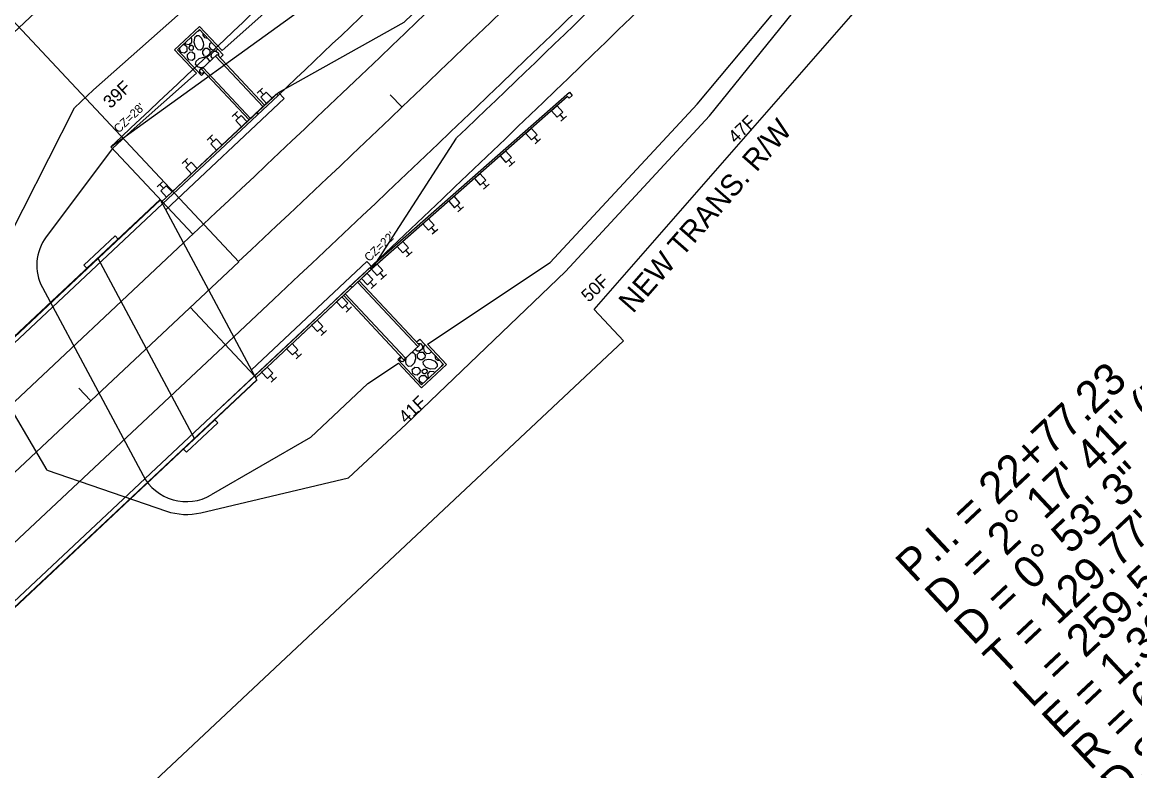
# Model space of a CAD drawing. Extents: x 1623239 to 1625698, y 1118659 to 1120751.
# Drawn here: x 1624416.9 to 1624676.8, y 1119574.5 to 1119749.3 of the extents above; entities that cross this region are included whole.
import ezdxf

# ---------------------------------------------------------------- set-up
doc = ezdxf.new("R2010")
doc.units = 0
for name, color, linetype in [('BR_CONCRETE', 7, 'Continuous'), ('BR_PROPOSED_TRAVELWAY', 7, 'Continuous'), ('Default', 7, 'Continuous'), ('Drainage-Trench', 7, 'Continuous'), ('RD_HC_CL_Rel', 7, 'Continuous'), ('RD_HC_Data', 7, 'Continuous'), ('RD_HC_Data_Tic', 7, 'Continuous'), ('RD_PD_BOC', 7, 'Continuous'), ('RD_PD_CstnLmt', 7, 'Continuous'), ('RD_PD_CstnLmt_TX', 7, 'Continuous'), ('RD_PD_DR_ErosCtrl', 7, 'Continuous'), ('RD_PD_Final_TrvlWay', 7, 'Continuous'), ('RD_PD_GR', 7, 'Continuous'), ('RD_PD_PaveDit', 7, 'Continuous'), ('RD_PD_PaveShd', 7, 'Continuous'), ('RD_PD_RW', 7, 'Continuous'), ('RD_Sketch8', 7, 'Continuous')]:
    doc.layers.add(name, color=color, linetype=linetype)

# ---------------------------------------------------------------- blocks, each defined once
blk = doc.blocks.new('Guardrail_MTBBC3_Transition')
at = {"layer": 'RD_PD_GR'}
for p, q in [((3.525, 3.75), (1.775, 3.75)), ((2.65, 2.5), (2.65, 3.75)), ((11.525, 3.75), (9.775, 3.75)), ((10.65, 2.5), (10.65, 3.75)), ((19.525, 3.75), (17.775, 3.75)), ((18.65, 2.5), (18.65, 3.75)), ((27.525, 3.75), (25.775, 3.75)), ((26.65, 2.5), (26.65, 3.75)), ((35.525, 3.75), (33.775, 3.75)), ((34.65, 2.5), (34.65, 3.75)), ((37, 0.5), (0, 0.5)), ((0, 0.5), (0, 0)), ((0, 0), (37, 0)), ((1.775, 0.5), (1.775, 2.5)), ((1.775, 2.5), (3.525, 2.5)), ((3.525, 0.5), (1.775, 0.5)), ((3.525, 2.5), (3.525, 0.5)), ((9.775, 0.5), (9.775, 2.5)), ((9.775, 2.5), (11.525, 2.5)), ((11.525, 0.5), (9.775, 0.5)), ((11.525, 2.5), (11.525, 0.5)), ((17.775, 0.5), (17.775, 2.5)), ((17.775, 2.5), (19.525, 2.5)), ((19.525, 0.5), (17.775, 0.5)), ((19.525, 2.5), (19.525, 0.5)), ((25.775, 0.5), (25.775, 2.5)), ((25.775, 2.5), (27.525, 2.5)), ((27.525, 0.5), (25.775, 0.5)), ((27.525, 2.5), (27.525, 0.5)), ((30.65, 0.5), (30.65, 0)), ((33.775, 0.5), (33.775, 2.5)), ((33.775, 2.5), (35.525, 2.5)), ((35.525, 0.5), (33.775, 0.5)), ((35.525, 2.5), (35.525, 0.5)), ((37, 0), (37, 0.5))]:
    blk.add_line(p, q, dxfattribs=at)

msp = doc.modelspace()

# ---------------------------------------------------------------- linework, layer by layer
at = {"layer": 'BR_CONCRETE'}
for p, q in [((1624343.39, 1119608.68), (1624449.15, 1119707.87)), ((1624343.45, 1119608.57), (1624449.22, 1119707.76)), ((1624343.94, 1119607.65), (1624449.7, 1119706.85)), ((1624449.15, 1119707.87), (1624471.75, 1119665.66)), ((1624434.57, 1119694.19), (1624457.17, 1119651.98)), ((1624365.44, 1119567.5), (1624471.2, 1119666.69)), ((1624365.93, 1119566.58), (1624471.69, 1119665.77)), ((1624365.99, 1119566.47), (1624471.75, 1119665.66))]:
    msp.add_line(p, q, dxfattribs=at)
for points in [[(1624432.01, 1119691.8), (1624431.33, 1119692.53), (1624438.62, 1119699.37), (1624439.31, 1119698.64)], [(1624455.3, 1119648.85), (1624454.61, 1119649.58), (1624461.91, 1119656.42), (1624462.59, 1119655.69)]]:
    msp.add_lwpolyline(points, close=True, dxfattribs=at)
at = {"layer": 'BR_PROPOSED_TRAVELWAY'}
for p, q in [((1624348.83, 1119598.53), (1624454.59, 1119697.72)), ((1624360.55, 1119576.62), (1624466.32, 1119675.81))]:
    msp.add_line(p, q, dxfattribs=at)
at = {"layer": 'Default'}
msp.add_line((1624365.44, 1119567.5), (1624471.2, 1119666.69), dxfattribs=at)
at = {"layer": 'Drainage-Trench'}
for p, q in [((1624453.22, 1119742.79), (1624458.32, 1119747.58)), ((1624463.88, 1119741.65), (1624458.32, 1119747.58)), ((1624458.77, 1119736.86), (1624453.22, 1119742.79)), ((1624458.82, 1119738.28), (1624462.47, 1119741.7)), ((1624462.1, 1119741.36), (1624473.18, 1119729.54)), ((1624462.47, 1119741.7), (1624473.54, 1119729.89)), ((1624463.15, 1119740.97), (1624463.88, 1119741.65)), ((1624458.77, 1119736.86), (1624459.5, 1119737.55)), ((1624458.82, 1119738.28), (1624469.9, 1119726.47)), ((1624459.18, 1119738.62), (1624470.26, 1119726.81)), ((1624509.36, 1119673.53), (1624495.26, 1119688.56)), ((1624509.73, 1119673.87), (1624495.63, 1119688.91)), ((1624506.08, 1119670.45), (1624491.98, 1119685.49)), ((1624506.45, 1119670.79), (1624492.35, 1119685.83)), ((1624509.05, 1119674.6), (1624509.77, 1119675.28)), ((1624509.77, 1119675.28), (1624515.33, 1119669.36)), ((1624506.08, 1119670.45), (1624509.73, 1119673.87)), ((1624504.67, 1119670.5), (1624505.4, 1119671.18)), ((1624504.67, 1119670.5), (1624510.22, 1119664.57)), ((1624510.22, 1119664.57), (1624515.33, 1119669.36))]:
    msp.add_line(p, q, dxfattribs=at)
at = {"layer": 'RD_HC_CL_Rel'}
msp.add_line((1624334.12, 1119568.29), (1624467.48, 1119693.35), dxfattribs=at)
msp.add_arc((1620034.69, 1124419.96), 6480, 313.16267, 315.457254, dxfattribs=at)
at = {"layer": 'RD_HC_Data'}
msp.add_line((1624467.48, 1119693.35), (1624367.16, 1119800.32), dxfattribs=at)
at = {"layer": 'RD_HC_Data_Tic'}
for p, q in [((1624505.66, 1119729.45), (1624502.9, 1119732.34)), ((1624432.86, 1119660.89), (1624430.12, 1119663.8))]:
    msp.add_line(p, q, dxfattribs=at)
at = {"layer": 'RD_PD_BOC'}
for p, q in [((1624449.36, 1119707.21), (1624476.75, 1119732.89)), ((1624476.75, 1119732.89), (1624478.11, 1119731.43)), ((1624478.11, 1119731.43), (1624450.44, 1119705.48)), ((1624497.46, 1119693.37), (1624470.47, 1119668.06)), ((1624498.83, 1119691.91), (1624497.46, 1119693.37)), ((1624471.45, 1119666.23), (1624498.83, 1119691.91))]:
    msp.add_line(p, q, dxfattribs=at)
at = {"layer": 'RD_PD_CstnLmt'}
for p, q in [((1624574.57, 1119730.15), (1624607.1, 1119768.89)), ((1624463.59, 1119742.69), (1624479.55, 1119756.84)), ((1624452.51, 1119742.81), (1624458.35, 1119748.28)), ((1624458.35, 1119748.28), (1624463.59, 1119742.69)), ((1624457.6, 1119737.39), (1624452.51, 1119742.81)), ((1624442.33, 1119723.86), (1624457.6, 1119737.39)), ((1624540.28, 1119693.12), (1624574.57, 1119730.15)), ((1624442.33, 1119723.86), (1624437.99, 1119719.78)), ((1624437.99, 1119719.78), (1624422.52, 1119699.13)), ((1624511.58, 1119674.09), (1624540.28, 1119693.12)), ((1624421.62, 1119687.33), (1624445.13, 1119643.41)), ((1624516.04, 1119669.34), (1624511.58, 1119674.09)), ((1624497.68, 1119664.88), (1624504.81, 1119669.61)), ((1624504.81, 1119669.61), (1624510.2, 1119663.87)), ((1624510.2, 1119663.87), (1624516.04, 1119669.34)), ((1624497.68, 1119664.88), (1624484.27, 1119652.31)), ((1624484.27, 1119652.31), (1624461.07, 1119638.88))]:
    msp.add_line(p, q, dxfattribs=at)
for centre, radius, start, end in [((1624431.33, 1119692.53), 11.01, 143.1621, 208.1627), ((1624455.3, 1119648.85), 11.53, 208.1627, 300.0691)]:
    msp.add_arc(centre, radius, start, end, dxfattribs=at)
at = {"layer": 'RD_PD_DR_ErosCtrl'}
for p, q in [((1624433.57, 1119733.46), (1624470.93, 1119766.57)), ((1624577.5, 1119727.43), (1624609.39, 1119766.95)), ((1624429.09, 1119729.26), (1624433.57, 1119733.46)), ((1624410.22, 1119692.05), (1624429.09, 1119729.26)), ((1624543.85, 1119691.09), (1624577.5, 1119727.43)), ((1624506.58, 1119655.4), (1624543.85, 1119691.09)), ((1624422.77, 1119644.63), (1624408.1, 1119669.48)), ((1624493.17, 1119642.83), (1624506.58, 1119655.4)), ((1624422.77, 1119644.63), (1624450.59, 1119635.11)), ((1624458.62, 1119634.71), (1624493.17, 1119642.83))]:
    msp.add_line(p, q, dxfattribs=at)
msp.add_arc((1624455.3, 1119648.85), 14.53, 251.1042, 283.2212, dxfattribs=at)
at = {"layer": 'RD_PD_Final_TrvlWay'}
for p, q in [((1624454.59, 1119697.72), (1624459.27, 1119702.11)), ((1624466.32, 1119675.81), (1624475.69, 1119684.6))]:
    msp.add_line(p, q, dxfattribs=at)
for radius in [6468, 6492]:
    msp.add_arc((1620034.69, 1124419.96), radius, 313.16267, 315.457254, dxfattribs=at)
at = {"layer": 'RD_PD_GR'}
for p, q in [((1624498.19, 1119692), (1624544.76, 1119732.93)), ((1624545.42, 1119732.18), (1624544.67, 1119731.52)), ((1624544.76, 1119732.93), (1624545.42, 1119732.18)), ((1624544.34, 1119731.89), (1624498.52, 1119691.62)), ((1624541.9, 1119729.75), (1624540.58, 1119728.59)), ((1624543.22, 1119728.25), (1624541.9, 1119729.75)), ((1624544.67, 1119731.52), (1624544.34, 1119731.89)), ((1624540.58, 1119728.59), (1624541.9, 1119727.09)), ((1624541.9, 1119727.09), (1624543.22, 1119728.25)), ((1624542.56, 1119727.67), (1624543.39, 1119726.73)), ((1624544.04, 1119727.31), (1624542.73, 1119726.15)), ((1624535.89, 1119724.47), (1624534.57, 1119723.31)), ((1624537.21, 1119722.96), (1624535.89, 1119724.47)), ((1624534.57, 1119723.31), (1624535.9, 1119721.81)), ((1624535.9, 1119721.81), (1624537.21, 1119722.96)), ((1624536.55, 1119722.39), (1624537.38, 1119721.45)), ((1624538.03, 1119722.03), (1624536.72, 1119720.87)), ((1624529.88, 1119719.18), (1624528.57, 1119718.03)), ((1624531.2, 1119717.68), (1624529.88, 1119719.18)), ((1624528.57, 1119718.03), (1624529.89, 1119716.53)), ((1624529.89, 1119716.53), (1624531.2, 1119717.68)), ((1624530.54, 1119717.1), (1624531.37, 1119716.17)), ((1624532.03, 1119716.74), (1624530.71, 1119715.59)), ((1624523.87, 1119713.9), (1624522.56, 1119712.75)), ((1624525.19, 1119712.4), (1624523.87, 1119713.9)), ((1624522.56, 1119712.75), (1624523.88, 1119711.25)), ((1624523.88, 1119711.25), (1624525.19, 1119712.4)), ((1624524.54, 1119711.82), (1624525.36, 1119710.88)), ((1624526.02, 1119711.46), (1624524.7, 1119710.31)), ((1624517.86, 1119708.62), (1624516.55, 1119707.47)), ((1624516.55, 1119707.47), (1624517.87, 1119705.96)), ((1624519.18, 1119707.12), (1624517.86, 1119708.62)), ((1624517.87, 1119705.96), (1624519.18, 1119707.12)), ((1624518.53, 1119706.54), (1624519.35, 1119705.6)), ((1624520.01, 1119706.18), (1624518.69, 1119705.02)), ((1624511.85, 1119703.34), (1624510.54, 1119702.18)), ((1624510.54, 1119702.18), (1624511.86, 1119700.68)), ((1624513.17, 1119701.84), (1624511.85, 1119703.34)), ((1624511.86, 1119700.68), (1624513.17, 1119701.84)), ((1624512.52, 1119701.26), (1624513.34, 1119700.32)), ((1624514, 1119700.9), (1624512.69, 1119699.74)), ((1624505.85, 1119698.06), (1624504.53, 1119696.9)), ((1624504.53, 1119696.9), (1624505.85, 1119695.4)), ((1624507.17, 1119696.56), (1624505.85, 1119698.06)), ((1624505.85, 1119695.4), (1624507.17, 1119696.56)), ((1624506.51, 1119695.98), (1624507.33, 1119695.04)), ((1624507.99, 1119695.62), (1624506.68, 1119694.46)), ((1624498.52, 1119691.62), (1624498.19, 1119692)), ((1624499.84, 1119692.78), (1624498.52, 1119691.62)), ((1624498.52, 1119691.62), (1624499.84, 1119690.12)), ((1624501.16, 1119691.27), (1624499.84, 1119692.78)), ((1624499.84, 1119690.12), (1624501.16, 1119691.27)), ((1624500.5, 1119690.7), (1624501.33, 1119689.76)), ((1624501.98, 1119690.34), (1624500.67, 1119689.18))]:
    msp.add_line(p, q, dxfattribs=at)
msp.add_arc((1620034.75, 1124419.9), 6458, 313.457809, 314.284639, dxfattribs=at)
at = {"layer": 'RD_PD_PaveDit'}
for p, q in [((1624459.46, 1119745.7), (1624460.24, 1119745.53)), ((1624462.32, 1119742.81), (1624462.66, 1119742.95)), ((1624461.35, 1119740.73), (1624461.42, 1119740.72)), ((1624459.11, 1119738.75), (1624459.48, 1119738.9)), ((1624508.69, 1119672.82), (1624508.68, 1119672.89)), ((1624510.83, 1119673.66), (1624510.99, 1119673.99)), ((1624506.57, 1119670.71), (1624506.75, 1119671.07)), ((1624513.53, 1119670.61), (1624513.41, 1119671.4))]:
    msp.add_line(p, q, dxfattribs=at)
for points in [[(1624455.03, 1119744.26), (1624455.89, 1119744.08), (1624456.51, 1119744.6), (1624456.52, 1119745.41), (1624456.26, 1119745.64)], [(1624459.28, 1119744.56), (1624458.91, 1119745.5), (1624458.26, 1119746.08), (1624457.7, 1119746.11), (1624457.19, 1119745.62), (1624457.04, 1119744.62), (1624457.35, 1119743.59), (1624457.96, 1119742.91), (1624458.57, 1119742.79), (1624459.14, 1119743.25), (1624459.32, 1119743.99), (1624459.28, 1119744.6)], [(1624457.88, 1119747.16), (1624458.18, 1119747.28), (1624458.39, 1119747.51)], [(1624459.14, 1119746.7), (1624459.12, 1119746.23), (1624459.46, 1119745.7)], [(1624453.64, 1119743.18), (1624453.63, 1119742.82), (1624453.96, 1119742.29)], [(1624453.96, 1119742.29), (1624454.82, 1119742.11), (1624455.44, 1119742.62), (1624455.45, 1119743.43), (1624454.84, 1119743.97), (1624454.45, 1119743.95)], [(1624454.94, 1119744.4), (1624455.03, 1119744.26)], [(1624456.03, 1119742.82), (1624456.54, 1119742.72), (1624456.92, 1119743.03), (1624456.92, 1119743.51), (1624456.55, 1119743.83), (1624456.17, 1119743.81), (1624455.84, 1119743.46), (1624455.83, 1119743.15), (1624456.03, 1119742.82)], [(1624459.36, 1119741.46), (1624460.22, 1119741.29), (1624460.84, 1119741.8), (1624460.85, 1119742.61), (1624460.23, 1119743.15), (1624459.59, 1119743.11), (1624459.05, 1119742.52), (1624459.02, 1119742), (1624459.36, 1119741.47)], [(1624461.15, 1119744.57), (1624460.68, 1119744.14), (1624460.55, 1119743.53), (1624461.01, 1119742.96), (1624461.76, 1119742.77), (1624462.37, 1119742.82)], [(1624455.77, 1119740.57), (1624456.63, 1119740.39), (1624457.25, 1119740.9), (1624457.26, 1119741.71), (1624456.64, 1119742.25), (1624456, 1119742.21), (1624455.46, 1119741.62), (1624455.43, 1119741.1), (1624455.77, 1119740.57)], [(1624460.65, 1119739.99), (1624460.67, 1119740.34), (1624460.17, 1119740.84), (1624459.17, 1119741), (1624458.14, 1119740.69), (1624457.46, 1119740.08), (1624457.34, 1119739.46), (1624457.8, 1119738.9), (1624458.55, 1119738.71), (1624459.15, 1119738.76)], [(1624462.83, 1119741.31), (1624462.84, 1119741.87), (1624462.22, 1119742.41), (1624461.58, 1119742.37), (1624461.04, 1119741.79), (1624461.01, 1119741.27), (1624461.35, 1119740.73)], [(1624459.02, 1119738.46), (1624458.67, 1119738.44), (1624458.35, 1119738.09), (1624458.33, 1119737.78), (1624458.53, 1119737.46)], [(1624458.53, 1119737.46), (1624459.05, 1119737.35), (1624459.41, 1119737.65)], [(1624509.36, 1119674.26), (1624509.93, 1119674.23), (1624510.43, 1119673.58), (1624510.35, 1119672.94), (1624509.73, 1119672.44), (1624509.21, 1119672.45), (1624508.69, 1119672.82)], [(1624509.3, 1119670.79), (1624509.17, 1119671.66), (1624509.73, 1119672.24), (1624510.54, 1119672.2), (1624511.03, 1119671.55), (1624510.95, 1119670.91), (1624510.33, 1119670.41), (1624509.81, 1119670.42), (1624509.3, 1119670.79)], [(1624512.51, 1119672.37), (1624512.05, 1119671.93), (1624511.43, 1119671.85), (1624510.9, 1119672.34), (1624510.76, 1119673.1), (1624510.85, 1119673.7)], [(1624505.24, 1119670.22), (1624505.17, 1119670.74), (1624505.49, 1119671.08)], [(1624506.28, 1119670.64), (1624506.24, 1119670.29), (1624505.87, 1119669.99), (1624505.55, 1119670), (1624505.24, 1119670.22)], [(1624507.91, 1119672.16), (1624508.26, 1119672.16), (1624508.73, 1119671.64), (1624508.82, 1119670.63), (1624508.45, 1119669.62), (1624507.79, 1119668.98), (1624507.17, 1119668.9), (1624506.64, 1119669.39), (1624506.5, 1119670.15), (1624506.59, 1119670.75)], [(1624512.38, 1119670.51), (1624513.29, 1119670.08), (1624513.83, 1119669.4), (1624513.83, 1119668.83), (1624513.31, 1119668.36), (1624512.3, 1119668.27), (1624511.28, 1119668.64), (1624510.65, 1119669.3), (1624510.56, 1119669.92), (1624511.06, 1119670.45), (1624511.82, 1119670.59), (1624512.42, 1119670.5)], [(1624514.51, 1119670.23), (1624514.04, 1119670.24), (1624513.53, 1119670.61)], [(1624508.17, 1119667.26), (1624508.05, 1119668.13), (1624508.6, 1119668.71), (1624509.41, 1119668.67), (1624509.9, 1119668.03), (1624509.83, 1119667.38), (1624509.21, 1119666.88), (1624508.68, 1119666.89), (1624508.17, 1119667.26)], [(1624510.44, 1119667.38), (1624510.37, 1119667.9), (1624510.7, 1119668.25), (1624511.18, 1119668.22), (1624511.48, 1119667.83), (1624511.43, 1119667.45), (1624511.06, 1119667.15), (1624510.75, 1119667.15), (1624510.44, 1119667.38)], [(1624511.81, 1119666.29), (1624511.69, 1119667.16), (1624512.24, 1119667.74), (1624513.05, 1119667.7), (1624513.26, 1119667.42)], [(1624514.89, 1119668.95), (1624515.02, 1119669.23), (1624515.27, 1119669.43)], [(1624509.77, 1119665.35), (1624509.65, 1119666.22), (1624510.2, 1119666.8), (1624511.01, 1119666.76), (1624511.51, 1119666.11), (1624511.46, 1119665.73)], [(1624510.65, 1119664.97), (1624510.29, 1119664.98), (1624509.77, 1119665.35)], [(1624511.95, 1119666.19), (1624511.81, 1119666.29)]]:
    msp.add_lwpolyline(points, dxfattribs=at)
at = {"layer": 'RD_PD_PaveShd'}
for p, q in [((1624476.75, 1119732.89), (1624506.13, 1119749.26)), ((1624498.83, 1119691.91), (1624518.37, 1119722.23))]:
    msp.add_line(p, q, dxfattribs=at)
for radius, start, end in [(6466, 313.75143, 315.213737), (6494, 313.664525, 315.457254)]:
    msp.add_arc((1620034.69, 1124419.96), radius, start, end, dxfattribs=at)
at = {"layer": 'RD_PD_RW'}
for p, q in [((1624550.56, 1119682.16), (1624683.49, 1119834.14)), ((1624236, 1119579.09), (1624454.27, 1119783.79)), ((1624550.56, 1119682.16), (1624557.4, 1119674.87)), ((1624338, 1119469.11), (1624557.4, 1119674.87))]:
    msp.add_line(p, q, dxfattribs=at)
at = {"layer": 'RD_Sketch8'}
for p, q in [((1624437.6, 1119720.17), (1624597.05, 1119835.21)), ((1624437.6, 1119720.17), (1624440.11, 1119722.53)), ((1624456.76, 1119699.75), (1624437.6, 1119720.17)), ((1624471.2, 1119666.69), (1624456.15, 1119682.73)), ((1624463.12, 1119659.11), (1624482.53, 1119677.31))]:
    msp.add_line(p, q, dxfattribs=at)
for radius, end in [(6502, 315.457254), (6440, 314.867171)]:
    msp.add_arc((1620034.69, 1124419.96), radius, 313.16267, end, dxfattribs=at)

# ---------------------------------------------------------------- block references
at = {"layer": 'RD_PD_Final_TrvlWay', "rotation": 43.16266984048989}
msp.add_blockref('Guardrail_MTBBC3_Transition', (1624449.7, 1119706.85), dxfattribs=at)
at = {"layer": 'RD_PD_Final_TrvlWay', "yscale": -1, "rotation": 43.16266984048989}
msp.add_blockref('Guardrail_MTBBC3_Transition', (1624471.2, 1119666.69), dxfattribs=at)

# ---------------------------------------------------------------- texts
at = {"layer": 'RD_HC_Data'}
for s, p in [('    = 2%%d 17\' 41" (LT)', (1624632.25, 1119610.81)), ('P.I. = 22+77.23', (1624625.41, 1119618.11)), ('D = 0%%d 53\' 3"', (1624639.09, 1119603.52)), ("T = 129.77'", (1624645.93, 1119596.22)), ("L = 259.51'", (1624652.77, 1119588.93)), ("R = 6,480.00'", (1624666.45, 1119574.34)), ('D', (1624632.25, 1119610.81)), ('D.S. = 45 MPH', (1624673.29, 1119567.05)), ("E = 1.30'", (1624659.61, 1119581.64))]:
    msp.add_text(s, height=7.5, rotation=43.1627, dxfattribs=at).set_placement(p)
at = {"layer": 'RD_PD_CstnLmt_TX'}
for s, rotation, p in [('39F', 43.1851, (1624437.54, 1119728.96)), ('47F', 44.0693, (1624583.61, 1119720.81)), ('50F', 43.6272, (1624549.25, 1119683.71)), ('41F', 43.1851, (1624506.58, 1119655.4))]:
    msp.add_text(s, height=3, rotation=rotation, dxfattribs=at).set_placement(p)
at = {"layer": 'RD_PD_RW'}
msp.add_text('NEW TRANS. R/W', height=5, rotation=48.8268, dxfattribs=at).set_placement((1624559.59, 1119681.09))
at = {"layer": 'RD_Sketch8'}
for s, rotation, p in [("CZ=28'", 43.1627, (1624439.43, 1119723.26)), ("CZ=22'", 43.3577, (1624497.96, 1119693.2))]:
    msp.add_text(s, height=2, rotation=rotation, dxfattribs=at).set_placement(p)

doc.saveas('drawing.dxf')
